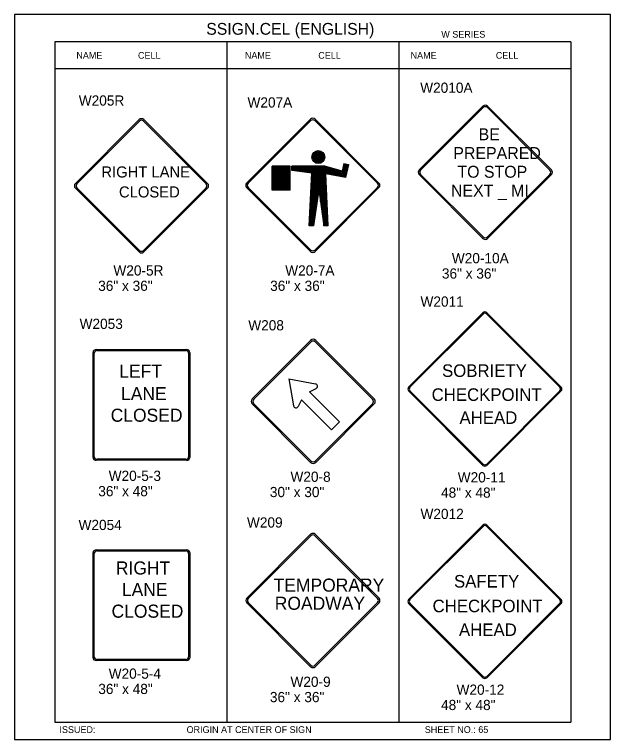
# Model space of a CAD drawing. Extents: x -5299 to 22597, y -19549 to -1808.
# Drawn here: x 3417 to 4118, y -7309 to -6456 of the extents above; entities that cross this region are included whole.
import ezdxf

# ---------------------------------------------------------------- set-up
doc = ezdxf.new("R2010")
doc.units = 0
for name, color, linetype in [('Level 1', 7, 'Continuous'), ('Level 2', 7, 'Continuous'), ('Level 3', 7, 'Continuous'), ('Level 62', 7, 'Continuous')]:
    doc.layers.add(name, color=color, linetype=linetype)

msp = doc.modelspace()

# ---------------------------------------------------------------- linework, layer by layer
at = {"layer": 'Level 1'}
for p, q in [((4071.64, -6488.59), (3464.63, -6488.59)), ((3464.63, -6488.59), (3464.63, -7288.59)), ((3666.97, -6488.59), (3666.97, -7288.59)), ((3869.29, -6489.04), (3869.29, -7289.04)), ((4071.64, -6488.59), (4071.64, -7288.59)), ((4071.64, -6520.26), (3464.63, -6520.26)), ((3893.06, -6639.19), (3968.18, -6564.07)), ((3894.85, -6639.42), (3968.4, -6565.86)), ((3973.32, -6565.86), (4046.88, -6639.42)), ((3973.55, -6564.07), (4048.67, -6639.19)), ((3488.71, -6655.11), (3563.83, -6579.99)), ((3569.2, -6579.99), (3644.32, -6655.11)), ((3690.2, -6654.56), (3765.34, -6579.43)), ((3770.71, -6579.43), (3845.85, -6654.56)), ((3490.5, -6655.33), (3564.06, -6581.78)), ((3568.97, -6581.78), (3642.53, -6655.33)), ((3691.99, -6654.79), (3765.57, -6581.22)), ((3770.49, -6581.22), (3844.06, -6654.79)), ((3720.15, -6663.09), (3720.15, -6634.65)), ((3741.48, -6634.65), (3720.15, -6634.65)), ((3721.16, -6663.09), (3721.16, -6634.65)), ((3722.18, -6663.09), (3722.18, -6634.65)), ((3723.2, -6663.09), (3723.2, -6634.65)), ((3724.21, -6663.09), (3724.21, -6634.65)), ((3725.23, -6663.09), (3725.23, -6634.65)), ((3726.24, -6663.09), (3726.24, -6634.65)), ((3727.26, -6663.09), (3727.26, -6634.65)), ((3728.28, -6663.09), (3728.28, -6634.65)), ((3729.29, -6663.09), (3729.29, -6634.65)), ((3730.31, -6663.09), (3730.31, -6634.65)), ((3731.32, -6663.09), (3731.32, -6634.65)), ((3732.34, -6663.09), (3732.34, -6634.65)), ((3733.35, -6663.09), (3733.35, -6634.65)), ((3734.37, -6663.09), (3734.37, -6634.65)), ((3735.39, -6663.09), (3735.39, -6634.65)), ((3736.4, -6663.09), (3736.4, -6634.65)), ((3737.42, -6663.09), (3737.42, -6634.65)), ((3738.43, -6663.09), (3738.43, -6634.65)), ((3739.45, -6663.09), (3739.45, -6634.65)), ((3740.47, -6663.09), (3740.47, -6634.65)), ((3741.48, -6663.09), (3741.48, -6634.65)), ((3782.12, -6634.65), (3743.51, -6634.65)), ((3743.51, -6639.73), (3743.51, -6634.65)), ((3782.12, -6635.66), (3743.51, -6635.66)), ((3782.12, -6636.68), (3743.51, -6636.68)), ((3782.12, -6637.69), (3743.51, -6637.69)), ((3782.12, -6638.71), (3743.51, -6638.71)), ((3766.88, -6642.77), (3743.51, -6639.73)), ((3767.01, -6641.77), (3743.64, -6638.72)), ((3767.14, -6640.76), (3743.78, -6637.71)), ((3767.28, -6639.75), (3743.91, -6636.7)), ((3767.9, -6644.81), (3767.9, -6638.71)), ((3768.91, -6644.81), (3768.91, -6638.71)), ((3769.93, -6644.81), (3769.93, -6638.71)), ((3770.95, -6644.81), (3770.95, -6638.71)), ((3771.96, -6644.81), (3771.96, -6638.71)), ((3772.98, -6676.3), (3772.98, -6638.71)), ((3773.99, -6670.2), (3773.99, -6638.71)), ((3775.01, -6666.14), (3775.01, -6638.71)), ((3776.02, -6669.19), (3776.02, -6638.71)), ((3777.04, -6676.3), (3777.04, -6638.71)), ((3778.06, -6644.81), (3778.06, -6638.71)), ((3779.07, -6644.81), (3779.07, -6638.71)), ((3780.09, -6644.81), (3780.09, -6638.71)), ((3800.98, -6645.61), (3780.66, -6639.51)), ((3801.27, -6644.64), (3780.95, -6638.54)), ((3781.1, -6644.81), (3781.1, -6638.71)), ((3801.56, -6643.66), (3781.24, -6637.57)), ((3801.86, -6642.69), (3781.54, -6636.59)), ((3802.15, -6641.72), (3781.83, -6635.62)), ((3802.44, -6640.74), (3782.12, -6634.65)), ((3782.12, -6644.81), (3782.12, -6638.71)), ((3783.14, -6644.81), (3783.14, -6638.71)), ((3804.89, -6631.69), (3801.5, -6646.97)), ((3804.47, -6631.6), (3802.44, -6640.74)), ((3805.88, -6631.91), (3802.49, -6647.19)), ((3806.87, -6632.13), (3803.48, -6647.41)), ((3804.47, -6631.6), (3809.85, -6632.79)), ((3807.87, -6632.35), (3804.47, -6647.63)), ((3808.86, -6632.57), (3805.46, -6647.85)), ((3809.85, -6632.79), (3806.45, -6648.07)), ((3763.83, -6704.75), (3766.88, -6642.77)), ((3764.85, -6704.8), (3767.9, -6642.82)), ((3765.86, -6704.85), (3768.91, -6642.87)), ((3766.88, -6704.9), (3769.93, -6642.92)), ((3767.89, -6704.95), (3770.94, -6642.97)), ((3768.91, -6705), (3771.95, -6643.02)), ((3770.69, -6689.49), (3772.97, -6643.07)), ((3771.96, -6676.3), (3771.96, -6644.81)), ((3779.23, -6688.48), (3777.05, -6644.09)), ((3781.06, -6705), (3778.06, -6644.04)), ((3778.06, -6676.3), (3778.06, -6644.81)), ((3782.08, -6704.95), (3779.08, -6643.99)), ((3783.09, -6704.9), (3780.09, -6643.94)), ((3800.69, -6646.58), (3780.37, -6640.49)), ((3784.1, -6704.85), (3781.11, -6643.89)), ((3785.12, -6704.8), (3782.12, -6643.84)), ((3806.45, -6648.07), (3783.14, -6643.79)), ((3786.13, -6704.75), (3783.14, -6643.79)), ((3806.64, -6647.07), (3783.32, -6642.79)), ((3968.18, -6719.68), (3893.06, -6644.56)), ((3968.4, -6717.9), (3894.85, -6644.34)), ((3971.03, -6641.97), (3971.03, -6641.97)), ((4046.88, -6644.34), (3973.32, -6717.89)), ((4048.67, -6644.56), (3973.55, -6719.68)), ((3563.83, -6735.6), (3488.71, -6660.48)), ((3564.06, -6733.81), (3490.5, -6660.25)), ((3566.46, -6657.73), (3566.46, -6657.73)), ((3642.53, -6660.25), (3568.97, -6733.81)), ((3644.32, -6660.48), (3569.2, -6735.6)), ((3765.34, -6735.07), (3690.2, -6659.93)), ((3765.57, -6733.28), (3691.99, -6659.71)), ((3741.48, -6663.09), (3720.15, -6663.09)), ((3768.26, -6657.36), (3768.26, -6657.36)), ((3774.98, -6662.25), (3768.91, -6704.75)), ((3844.06, -6659.71), (3770.49, -6733.28)), ((3845.85, -6659.93), (3770.71, -6735.07)), ((3774.98, -6662.25), (3781.05, -6704.75)), ((3771.99, -6675.87), (3767.93, -6704.32)), ((3777.98, -6675.87), (3782.04, -6704.32)), ((3768.91, -6704.75), (3763.83, -6704.75)), ((3786.13, -6704.75), (3781.05, -6704.75)), ((3880.7, -6894.45), (3968.1, -6807.05)), ((3882.23, -6894.64), (3968.29, -6808.58)), ((3972.51, -6808.58), (4058.56, -6894.64)), ((3972.7, -6807.05), (4060.1, -6894.45)), ((3696.71, -6908.28), (3765.48, -6839.51)), ((3698.7, -6908.53), (3765.73, -6841.5)), ((3771.21, -6841.5), (3838.24, -6908.53)), ((3771.46, -6839.51), (3840.23, -6908.28)), ((3513.31, -6850.38), (3619.57, -6850.38)), ((3514.41, -6851.6), (3618.46, -6851.6)), ((3509.51, -6977.24), (3509.51, -6853.63)), ((3510.93, -6976.29), (3510.93, -6854.58)), ((3621.94, -6854.58), (3621.94, -6976.29)), ((3623.36, -6853.63), (3623.36, -6977.24)), ((3739.63, -6884.91), (3745.38, -6916.5)), ((3739.63, -6884.91), (3771.21, -6890.66)), ((3764.04, -6900.13), (3771.9, -6895.95)), ((3764.04, -6900.13), (3799.31, -6935.39)), ((3968.1, -6986.45), (3880.7, -6899.05)), ((3968.29, -6984.92), (3882.23, -6898.86)), ((3970.4, -6896.75), (3970.4, -6896.75)), ((4058.56, -6898.86), (3972.51, -6984.92)), ((4060.1, -6899.05), (3972.7, -6986.45)), ((3754.85, -6909.33), (3750.66, -6917.19)), ((3790.11, -6944.59), (3754.85, -6909.33)), ((3767.54, -6910.61), (3767.54, -6910.61)), ((3566.36, -6915.32), (3566.36, -6915.32)), ((3765.48, -6983.03), (3696.71, -6914.26)), ((3765.73, -6981.03), (3698.7, -6914.01)), ((3838.24, -6914.01), (3771.21, -6981.03)), ((3840.23, -6914.26), (3771.46, -6983.03)), ((3799.31, -6935.39), (3790.11, -6944.59)), ((3619.57, -6980.49), (3513.31, -6980.49)), ((3618.46, -6979.27), (3514.41, -6979.27)), ((3880.7, -7144.11), (3968.1, -7056.71)), ((3972.7, -7056.71), (4060.1, -7144.11)), ((3882.23, -7144.3), (3968.29, -7058.24)), ((3972.51, -7058.24), (4058.56, -7144.3)), ((3690.28, -7142.69), (3765.41, -7067.55)), ((3692.06, -7142.91), (3765.64, -7069.34)), ((3770.56, -7069.34), (3844.13, -7142.91)), ((3770.78, -7067.55), (3845.92, -7142.69)), ((3509.51, -7212.7), (3509.51, -7089.1)), ((3510.93, -7211.76), (3510.93, -7090.05)), ((3513.31, -7085.85), (3619.57, -7085.85)), ((3514.41, -7087.07), (3618.46, -7087.07)), ((3621.94, -7090.05), (3621.94, -7211.76)), ((3623.36, -7089.1), (3623.36, -7212.7)), ((3566.06, -7150.88), (3566.06, -7150.88)), ((3765.41, -7223.2), (3690.28, -7148.06)), ((3765.64, -7221.41), (3692.06, -7147.84)), ((3767.69, -7145.49), (3767.69, -7145.49)), ((3844.13, -7147.84), (3770.56, -7221.41)), ((3845.92, -7148.06), (3770.78, -7223.2)), ((3968.1, -7236.11), (3880.7, -7148.71)), ((3968.29, -7234.57), (3882.23, -7148.52)), ((3970.4, -7146.41), (3970.4, -7146.41)), ((4058.56, -7148.52), (3972.51, -7234.57)), ((4060.1, -7148.71), (3972.7, -7236.11)), ((3619.57, -7215.96), (3513.31, -7215.96)), ((3618.46, -7214.74), (3514.41, -7214.74)), ((3464.63, -7288.59), (4071.64, -7288.59))]:
    msp.add_line(p, q, dxfattribs=at)
for centre, radius in [((3774.5, -6623.98), 7.64), ((3774.42, -6624.06), 6.49), ((3774.36, -6624.12), 5.52), ((3774.3, -6624.17), 4.69), ((3774.26, -6624.22), 3.99), ((3774.37, -6624.26), 3.39), ((3774.47, -6624.3), 2.88), ((3774.55, -6624.32), 2.45), ((3774.68, -6624.37), 1.77), ((3774.86, -6624.43), 0.815), ((3774.92, -6624.46), 0.458)]:
    msp.add_circle(centre, radius, dxfattribs=at)
for centre, radius, start, end in [((3970.86, -6566.75), 3.79, 45, 135), ((3970.86, -6568.32), 3.48, 45, 135), ((3566.52, -6582.67), 3.79, 45, 135), ((3768.03, -6582.11), 3.8, 45, 135), ((3768.03, -6583.67), 3.48, 45, 135), ((3566.52, -6584.23), 3.48, 45, 135), ((3895.74, -6641.88), 3.79, 135, 225), ((3897.3, -6641.88), 3.48, 135, 225), ((4044.42, -6641.88), 3.48, 315, 45), ((4045.99, -6641.88), 3.79, 315, 45), ((3491.39, -6657.79), 3.79, 135, 225), ((3492.96, -6657.79), 3.48, 135, 225), ((3640.07, -6657.79), 3.48, 315, 45), ((3641.64, -6657.79), 3.79, 315, 45), ((3692.89, -6657.25), 3.8, 135, 225), ((3694.45, -6657.25), 3.48, 135, 225), ((3841.6, -6657.25), 3.48, 315, 45), ((3843.16, -6657.25), 3.8, 315, 45), ((3970.86, -6717), 3.79, 225, 315), ((3970.86, -6715.44), 3.48, 225, 315), ((3768.03, -6730.82), 3.48, 225, 315), ((3566.52, -6732.92), 3.79, 225, 315), ((3566.52, -6731.35), 3.48, 225, 315), ((3768.03, -6732.39), 3.8, 225, 315), ((3970.4, -6809.35), 3.25, 45, 135), ((3970.4, -6810.69), 2.98, 45, 135), ((3768.47, -6842.5), 4.23, 45, 135), ((3768.47, -6844.24), 3.88, 45, 135), ((3770.54, -6893.46), 2.87, 298.62635, 76.96763), ((3883, -6896.75), 3.25, 135, 225), ((3884.34, -6896.75), 2.98, 135, 225), ((4056.46, -6896.75), 2.98, 315, 45), ((4057.8, -6896.75), 3.25, 315, 45), ((3699.7, -6911.27), 4.23, 135, 225), ((3701.44, -6911.27), 3.88, 135, 225), ((3835.5, -6911.27), 3.88, 315, 45), ((3837.24, -6911.27), 4.23, 315, 45), ((3748.14, -6915.85), 2.85, 192.66558, 332.14513), ((3768.47, -6980.04), 4.23, 225, 315), ((3768.47, -6978.29), 3.88, 225, 315), ((3970.4, -6984.15), 3.25, 225, 315), ((3970.4, -6982.81), 2.98, 225, 315), ((3970.4, -7059.01), 3.25, 45, 135), ((3970.4, -7060.35), 2.98, 45, 135), ((3768.1, -7070.24), 3.8, 45, 135), ((3768.1, -7071.8), 3.48, 45, 135), ((3692.96, -7145.38), 3.8, 135, 225), ((3694.52, -7145.38), 3.48, 135, 225), ((3841.67, -7145.38), 3.48, 315, 45), ((3843.23, -7145.38), 3.8, 315, 45), ((3883, -7146.41), 3.25, 135, 225), ((3884.34, -7146.41), 2.98, 135, 225), ((4056.46, -7146.41), 2.98, 315, 45), ((4057.8, -7146.41), 3.25, 315, 45), ((3768.1, -7220.51), 3.8, 225, 315), ((3768.1, -7218.95), 3.48, 225, 315), ((3970.4, -7233.81), 3.25, 225, 315), ((3970.4, -7232.47), 2.98, 225, 315)]:
    msp.add_arc(centre, radius, start, end, dxfattribs=at)
for centre, major_axis, start_param, end_param in [((3513.31, -6853.63), (-3.8, 0), 4.712389, 6.283185), ((3514.41, -6854.58), (-3.48, 0), 4.712389, 6.283185), ((3618.46, -6854.58), (-3.48, 0), 3.141593, 4.712389), ((3619.57, -6853.63), (3.8, 0), 0, 1.570796), ((3513.31, -6977.23), (3.8, 0), 3.141593, 4.712389), ((3514.41, -6976.29), (3.48, 0), 3.141593, 4.712389), ((3618.46, -6976.29), (3.48, 0), 4.712389, 6.283185), ((3619.57, -6977.23), (3.8, 0), 4.712389, 6.283185), ((3513.31, -7089.1), (-3.8, 0), 4.712389, 6.283185), ((3514.41, -7090.05), (-3.48, 0), 4.712389, 6.283185), ((3618.46, -7090.05), (-3.48, 0), 3.141593, 4.712389), ((3619.57, -7089.1), (3.8, 0), 0, 1.570796), ((3513.31, -7212.7), (3.8, 0), 3.141593, 4.712389), ((3514.41, -7211.76), (3.48, 0), 3.141593, 4.712389), ((3618.46, -7211.76), (3.48, 0), 4.712389, 6.283185), ((3619.57, -7212.7), (3.8, 0), 4.712389, 6.283185)]:
    msp.add_ellipse(centre, major_axis=major_axis, ratio=0.857082, start_param=start_param, end_param=end_param, dxfattribs=at)
at = {"layer": 'Level 62'}
msp.add_lwpolyline([(3417.12, -7308.78), (4118.17, -7308.78), (4118.17, -6456.4), (3417.12, -6456.4)], close=True, dxfattribs=at)

# ---------------------------------------------------------------- texts
at = {"layer": 'Level 1'}
for s, height, p in [('BE', 14, (3963.03, -6604.27)), ('PREPARED', 14, (3933.26, -6626.28)), ('RIGHT LANE', 13, (3519.31, -6648.03)), ('TO STOP', 14, (3938.1, -6648.3)), ('NEXT _ MI', 14, (3930.51, -6670.44)), ('CLOSED', 13, (3540.01, -6671.5)), ('LEFT', 15.368, (3540.42, -6883.39)), ('SOBRIETY', 14.753, (3920.02, -6882.48)), ('LANE', 15.368, (3542.45, -6909.81)), ('CHECKPOINT', 14.753, (3907.78, -6910.67)), ('CLOSED', 15.368, (3530.26, -6935.21)), ('AHEAD', 14.753, (3940.57, -6937.74)), ('RIGHT', 15.368, (3536.35, -7114.8)), ('SAFETY', 14.753, (3934.08, -7130.13)), ('LANE', 15.368, (3543.47, -7140.2)), ('TEMPORARY', 15.368, (3721.88, -7134.97)), ('ROADWAY', 15.368, (3723.26, -7156.3)), ('CLOSED', 15.368, (3531.27, -7165.6)), ('CHECKPOINT', 14.753, (3908.88, -7159.15)), ('AHEAD', 14.753, (3939.93, -7187.11))]:
    msp.add_text(s, height=height, dxfattribs=at).set_placement(p)
at = {"layer": 'Level 2'}
for s, p in [('W2010A', (3894.34, -6548.47)), ('W205R', (3492.74, -6563.52)), ('W207A', (3691.21, -6565.8)), ('W2011', (3894.67, -6799.89)), ('W2053', (3493.7, -6826.09)), ('W208', (3692.1, -6827.79)), ('W2012', (3894.67, -7049.55)), ('W209', (3690.56, -7059.59)), ('W2054', (3492.46, -7062.53))]:
    msp.add_text(s, height=12, dxfattribs=at).set_placement(p)
at = {"layer": 'Level 3'}
for s, height, p in [('SSIGN.CEL (ENGLISH)', 13.8566, (3642.7, -6480.2)), ('W SERIES', 7.918, (3919.14, -6483.64)), ('NAME', 7.918, (3489.91, -6508.42)), ('CELL', 7.918, (3562.36, -6508.42)), ('NAME', 7.918, (3688.11, -6508.42)), ('CELL', 7.918, (3774.43, -6508.42)), ('NAME', 7.918, (3883.03, -6508.42)), ('CELL', 7.918, (3983.25, -6508.42)), ('W20-10A', 12, (3931.56, -6748.9)), ('W20-5R', 12, (3533.49, -6763.32)), ('W20-7A', 12, (3735.57, -6763.32)), ('36" x 36"', 12, (3919.84, -6766.9)), ('36" x 36"', 12, (3515.58, -6781.32)), ('36" x 36"', 12, (3717.85, -6781.32)), ('W20-5-3', 12, (3527.9, -7004.76)), ('W20-8', 12, (3741.74, -7005.83)), ('W20-11', 12, (3938.47, -7006.52)), ('36" x 48"', 12, (3515.66, -7022.76)), ('30" x 30"', 12, (3717.5, -7023.83)), ('48" x 48"', 12, (3918.86, -7024.52)), ('W20-5-4', 12, (3527.9, -7237.33)), ('W20-9', 12, (3741.73, -7246.88)), ('36" x 48"', 12, (3515.66, -7255.33)), ('W20-12', 12, (3937.1, -7256.18)), ('36" x 36"', 12, (3717.54, -7264.88)), ('48" x 48"', 12, (3918.86, -7274.18)), ('ISSUED:', 7.918, (3469.99, -7301.08)), ('ORIGIN AT CENTER OF SIGN', 7.9181, (3619.52, -7301.08)), ('SHEET NO.: 65', 7.918, (3899.68, -7301.08))]:
    msp.add_text(s, height=height, dxfattribs=at).set_placement(p)

doc.saveas('drawing.dxf')
